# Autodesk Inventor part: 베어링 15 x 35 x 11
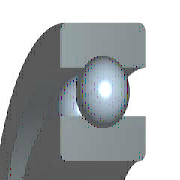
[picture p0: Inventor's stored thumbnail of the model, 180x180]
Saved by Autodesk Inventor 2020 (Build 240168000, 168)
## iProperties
Created: 2012-02
Part Number: 베어링 15 x 35 x 11
Material: 강철, 연강
Description: 깊은 그루브 볼 베어링
Document SubType Name: Modeling
Standard: KS B 2023
Designer: mduedu
Standards Organization: KS
Language: ko-KR
Size Designation: 6202 - 15 x 35 x 11
Categories: <MemberInstance><Categories><Category DisplayName="샤프트 부품" InternalName="7f7aeb1f-a693-4053-b835-cee3144e0d98" Mnemonic="SHFT"><Category DisplayName="베어링" Inter
Density: 1 g/cm^3
Appearance: 노란색
IsCustomPart: 1
Author: mduedu
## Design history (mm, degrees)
sketch "스케치" dims "d0" = 5.2 (= -0.26 x WD + 0.26 x BD)
  geometry: L1 (2.9, 12.5)-(8.1, 12.5); L2 (5.5, 12.5)-(5.5, 9.9); L3 (5.5, 12.5)-(5.5, 15.1); L4 (3.568, 10.76)-(0, 10.76); L5 (0, 7.5)-(11, 7.5); L6 (3.568, 14.24)-(0, 14.24); L7 (0, 17.5)-(11, 17.5); L8 (11, 7.5)-(11, 10.76); L9 (7.432, 10.76)-(11, 10.76); L10 (7.432, 14.24)-(11, 14.24); L11 (11, 17.5)-(11, 14.24); L12 (-1.4, 0)-(8.4, 0) reference; L13 (0, -0.3)-(0, 5.3) reference
  constraints: 22 end point, 4 point on line, 2 collinear, 2 perpendicular, 2 symmetric about line, 1 midpoint, 1 parallel, 14 other
  dimensions: "d9" = 15 diameter of L5 L12 (= WD); "d11" = 35 diameter of L7 L12 (= BD); "d12" = 11 distance between parallel lines of L8 L13 (= KB); "d13" = 21.52 diameter of L9 L12 (= 0.326 x BD + 0.674 x WD)
revolve "본체" stored, may be unused: angle "d6" = 90 deg
revolve "볼" stored, may be unused: angle "d7" = 90 deg
pattern_circular "IDS_ARRAYBALL[SIMPL:T]" dims angle "d3" = 360 deg
body "Solid1"
fillet "모깎기1" dims "d1" = 0.6 (= KRS)
other parameters: "WD" = 15 [user parameter; used in 5 equation terms], "BD" = 35 [user parameter; used in 5 equation terms], "KB" = 11 [user parameter; used in 1 equation term], "KRS" = 0.6 [user parameter; used in 1 equation term], "d4" = 0, "d5" = 0, "d8" = 0, "d14" = 0, "d15" = 0, "BBA" = 0 [user parameter], "BC0" = 3750000 [user parameter], "BC" = 7800000 [user parameter], "BR" = 17.5 (= 0.5 x BD) [user parameter], "WR" = 7.5 (= 0.5 x WD) [user parameter]
